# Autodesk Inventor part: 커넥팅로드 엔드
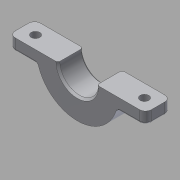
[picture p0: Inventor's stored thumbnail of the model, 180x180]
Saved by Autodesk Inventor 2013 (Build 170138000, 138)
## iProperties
Created: 2016-11
Part Number: 커넥팅로드 엔드
Material: 알루미늄 6061
Document SubType Name: Modeling
Designer: mduedu
Density: 2.71 g/cm^3
Mass: 24.1426 g
Surface Area: 36.9806 cm^2
Volume: 8.9087 cm^3
Author: mduedu
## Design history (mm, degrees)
sketch "스케치1" dims "d0" = 42, "d3" = 20
  geometry: L1 (0, 0)-(0, 114); L2 (-7.5, 107.386)-(-12.5, 16.875); L3 (7.5, 107.386)-(12.5, 16.875); C1 r 10 at (0, 0); C2 r 6.5 at (0, 114); 3 further points
  constraints: 6 end point, 4 coincident, 2 centre point, 2 symmetric about line, 1 vertical, 6 other
  dimensions: "d1" = 20 diameter of C1; "d2" = 13 diameter of C2; "d4" = 114 distance of L1.start L1.end; "d6" = 12.5 distance from line of L1 L2.end; "d7" = 7.5 distance from line of L1 L2.start
extrude "돌출1" new body sketch "스케치1" stored distance "d8" = 13; taper "d9" = 0 deg
extrude "돌출2" join sketch "스케치1" stored distance "d10" = 20; taper "d11" = 0 deg
sketch "스케치2"
  geometry: L1 (-7.5, 107.386)-(-12.5, 16.875) reference; L2 (7.5, 107.386)-(12.5, 16.875) reference; A1 r 10 centre (0, 114) between (-7.5, 107.386) and (7.5, 107.386) reference; A2 r 21 centre (0, 0) between (-12.5, 16.875) and (12.5, 16.875) reference; 1 further point
extrude "돌출3" join sketch "스케치2" stored distance "d12" = 8; taper "d13" = 0 deg
sketch "스케치3"
  geometry: L1 (-7.5, 107.386)-(-12.5, 16.875) reference; L2 (7.5, 107.386)-(12.5, 16.875) reference; L3 (-4.209, 94.448)-(-7.768, 30.011); L4 (4.209, 94.448)-(7.768, 30.011); L5 (0, 94)-(0, 31); A1 r 10 centre (0, 114) between (-7.5, 107.386) and (7.5, 107.386) reference; A2 r 21 centre (0, 0) between (-12.5, 16.875) and (12.5, 16.875) reference; A3 r 20 centre (0, 114) between (-4.209, 94.448) and (4.209, 94.448); A4 r 31 centre (0, 0) between (7.768, 30.011) and (-7.768, 30.011); 1 further point
  constraints: 6 end point, 6 point on circle, 2 centre point, 2 parallel, 1 symmetric about line, 1 vertical alignment
  dimensions: "d18" = 10 radial gap between concentric circles of A3 A1; "d19" = 10 radial gap between concentric circles of A2 A4; "d20" = 4 distance between parallel lines of L3 L1
extrude "돌출4" cut sketch "스케치3" distance "d21" = 2; taper "d22" = 0 deg
fillet "모깎기1" dims "d23" = 3
fillet "모깎기2" dims "d24" = 2
fillet "모깎기3" dims "d25" = 2
chamfer "모따기1" distance "d26" = 1; stored, may be unused: second distance "d27" = 2, angle "d28" = 45 deg
sketch "스케치4"
  geometry: L1 (-35, -6)-(-20.125, -6); L2 (35, -6)-(35, 6); L3 (35, 6)-(20.125, 6); L4 (-35, 6)-(-35, -6); L5 (-35, -6)-(35, 6); L6 (35, -6)-(-35, 6); L7 (-20.125, 6)-(-35, 6); L8 (20.125, 6)-(-20.125, 6); L9 (20.125, -6)-(35, -6); L10 (-20.125, -6)-(20.125, -6); A1 r 21 centre (0, 0) between (-20.125, 6) and (20.125, 6) reference; 1 further point
  constraints: 20 end point, 10 parallel, 4 point on circle, 3 horizontal, 3 perpendicular, 2 midpoint
  dimensions: "d29" = 70 distance of L1.start L2.start; "d31" = 12 distance of L2.start L2.end
extrude "돌출5" join sketch "스케치4" stored distance "d32" = 0; taper "d33" = 0 deg
fillet "모깎기4" dims "d34" = 3
fillet "모깎기5" dims "d35" = 1
fillet "모깎기6" dims "d36" = 1
sketch "스케치5"
  geometry: L1 (1, 0)-(1, 7) reference; L2 (-24, 13.5)-(-44, 13.5) reference; L3 (-44, -6.5)-(-24, -6.5) reference; L4 (-34, 13.5)-(-34, -6.5); 3 further points
  constraints: 2 end point, 2 midpoint, 1 horizontal alignment, 1 symmetric about line
  dimensions: "d37" = 7 distance from line of point (-6, 3.5) L1
feature "분할1"
sketch "스케치6"
  geometry: 2 further points
  constraints: 2 other
hole "구멍1" sketch "스케치6" at (-62, 3.5), (-6, 3.5) diameter "d38" = 4.5; stored, may be unused: countersink angle "d42" = 90 deg, drill point angle "d44" = 0 deg; dims "d39" = 6, "d40" = 4, "d41" = 2, "d43" = 8
node "솔리드1"
mirror "대칭1"
other parameters: "d16" = 4, "d17" = 4
